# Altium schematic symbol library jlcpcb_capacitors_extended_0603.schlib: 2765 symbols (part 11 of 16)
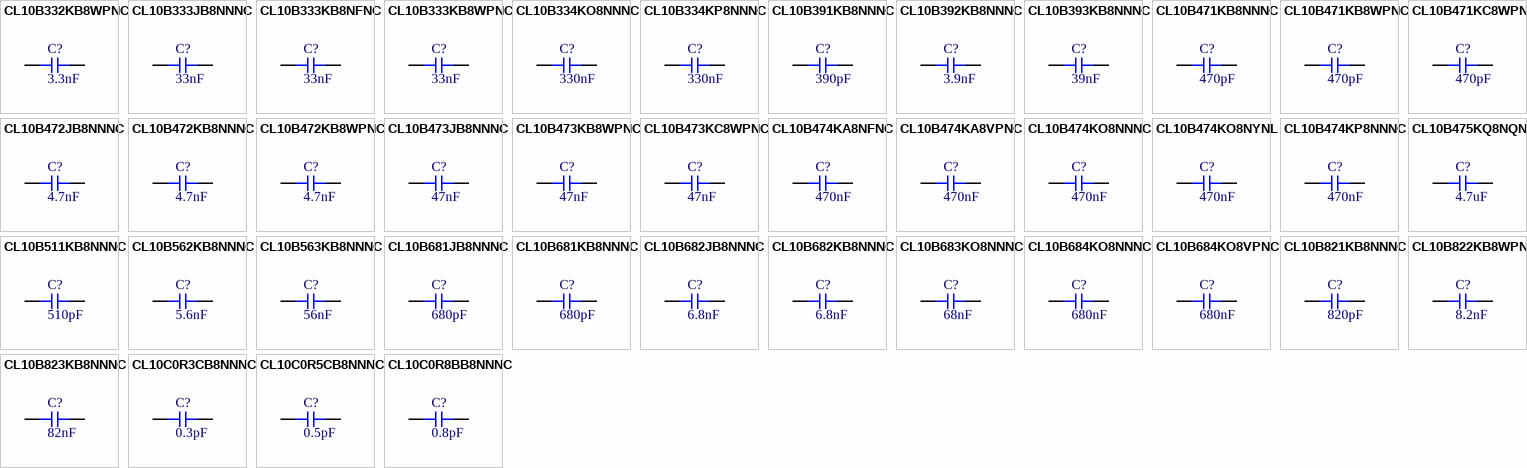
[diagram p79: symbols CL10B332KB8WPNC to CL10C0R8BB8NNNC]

## CL10B333KB8NFNC
designator C?  Capacitance: 33nF  (hidden comment: *)
Capacitor, Ceramic (MLCC), 33nF, ±10%, 50V, X7R, ±10%, SMD 0603; Manufacturer: Samsung Electro-Mechanics; Manufacturer Part Number: CL10B333KB8NFNC
footprint CAP-0603 (0603 (1608M) Capacitor)
pins: 1, 2

## CL10B333KB8WPNC
designator C?  Capacitance: 33nF  (hidden comment: *)
Capacitor, Ceramic (MLCC), 33nF, ±10%, 50V, X7R, ±10%, SMD 0603; Manufacturer: Samsung Electro-Mechanics; Manufacturer Part Number: CL10B333KB8WPNC
footprint CAP-0603 (0603 (1608M) Capacitor)
pins: 1, 2

## CL10B334KO8NNNC
designator C?  Capacitance: 330nF  (hidden comment: *)
Capacitor, Ceramic (MLCC), 330nF, ±10%, 16V, X7R, ±10%, SMD 0603; Manufacturer: Samsung Electro-Mechanics; Manufacturer Part Number: CL10B334KO8NNNC
footprint CAP-0603 (0603 (1608M) Capacitor)
pins: 1, 2

## CL10B334KP8NNNC
designator C?  Capacitance: 330nF  (hidden comment: *)
Capacitor, Ceramic (MLCC), 330nF, ±10%, 10V, X7R, ±10%, SMD 0603; Manufacturer: Samsung Electro-Mechanics; Manufacturer Part Number: CL10B334KP8NNNC
footprint CAP-0603 (0603 (1608M) Capacitor)
pins: 1, 2

## CL10B391KB8NNNC
designator C?  Capacitance: 390pF  (hidden comment: *)
Capacitor, Ceramic (MLCC), 390pF, ±10%, 50V, X7R, ±10%, SMD 0603; Manufacturer: Samsung Electro-Mechanics; Manufacturer Part Number: CL10B391KB8NNNC
footprint CAP-0603 (0603 (1608M) Capacitor)
pins: 1, 2

## CL10B392KB8NNNC
designator C?  Capacitance: 3.9nF  (hidden comment: *)
Capacitor, Ceramic (MLCC), 3.9nF, ±10%, 50V, X7R, ±10%, SMD 0603; Manufacturer: Samsung Electro-Mechanics; Manufacturer Part Number: CL10B392KB8NNNC
footprint CAP-0603 (0603 (1608M) Capacitor)
pins: 1, 2

## CL10B393KB8NNNC
designator C?  Capacitance: 39nF  (hidden comment: *)
Capacitor, Ceramic (MLCC), 39nF, ±10%, 50V, X7R, ±10%, SMD 0603; Manufacturer: Samsung Electro-Mechanics; Manufacturer Part Number: CL10B393KB8NNNC
footprint CAP-0603 (0603 (1608M) Capacitor)
pins: 1, 2

## CL10B471KB8NNNC
designator C?  Capacitance: 470pF  (hidden comment: *)
Capacitor, Ceramic (MLCC), 470pF, ±10%, 50V, X7R, ±10%, SMD 0603; Manufacturer: Samsung Electro-Mechanics; Manufacturer Part Number: CL10B471KB8NNNC
footprint CAP-0603 (0603 (1608M) Capacitor)
pins: 1, 2

## CL10B471KB8WPNC
designator C?  Capacitance: 470pF  (hidden comment: *)
Capacitor, Ceramic (MLCC), 470pF, ±10%, 50V, X7R, ±10%, SMD 0603; Manufacturer: Samsung Electro-Mechanics; Manufacturer Part Number: CL10B471KB8WPNC
footprint CAP-0603 (0603 (1608M) Capacitor)
pins: 1, 2

## CL10B471KC8WPNC
designator C?  Capacitance: 470pF  (hidden comment: *)
Capacitor, Ceramic (MLCC), 470pF, ±10%, 100V, X7R, ±10%, SMD 0603; Manufacturer: Samsung Electro-Mechanics; Manufacturer Part Number: CL10B471KC8WPNC
footprint CAP-0603 (0603 (1608M) Capacitor)
pins: 1, 2

## CL10B472JB8NNNC
designator C?  Capacitance: 4.7nF  (hidden comment: *)
Capacitor, Ceramic (MLCC), 4.7nF, ±5%, 50V, X7R, ±5%, SMD 0603; Manufacturer: Samsung Electro-Mechanics; Manufacturer Part Number: CL10B472JB8NNNC
footprint CAP-0603 (0603 (1608M) Capacitor)
pins: 1, 2

## CL10B472KB8NNNC
designator C?  Capacitance: 4.7nF  (hidden comment: *)
Capacitor, Ceramic (MLCC), 4.7nF, ±10%, 50V, X7R, ±10%, SMD 0603; Manufacturer: Samsung Electro-Mechanics; Manufacturer Part Number: CL10B472KB8NNNC
footprint CAP-0603 (0603 (1608M) Capacitor)
pins: 1, 2

## CL10B472KB8WPNC
designator C?  Capacitance: 4.7nF  (hidden comment: *)
Capacitor, Ceramic (MLCC), 4.7nF, ±10%, 50V, X7R, ±10%, SMD 0603; Manufacturer: Samsung Electro-Mechanics; Manufacturer Part Number: CL10B472KB8WPNC
footprint CAP-0603 (0603 (1608M) Capacitor)
pins: 1, 2

## CL10B473JB8NNNC
designator C?  Capacitance: 47nF  (hidden comment: *)
Capacitor, Ceramic (MLCC), 47nF, ±5%, 50V, X7R, ±5%, SMD 0603; Manufacturer: Samsung Electro-Mechanics; Manufacturer Part Number: CL10B473JB8NNNC
footprint CAP-0603 (0603 (1608M) Capacitor)
pins: 1, 2

## CL10B473KB8WPNC
designator C?  Capacitance: 47nF  (hidden comment: *)
Capacitor, Ceramic (MLCC), 47nF, ±10%, 50V, X7R, ±10%, SMD 0603; Manufacturer: Samsung Electro-Mechanics; Manufacturer Part Number: CL10B473KB8WPNC
footprint CAP-0603 (0603 (1608M) Capacitor)
pins: 1, 2

## CL10B473KC8WPNC
designator C?  Capacitance: 47nF  (hidden comment: *)
Capacitor, Ceramic (MLCC), 47nF, ±10%, 100V, X7R, ±10%, SMD 0603; Manufacturer: Samsung Electro-Mechanics; Manufacturer Part Number: CL10B473KC8WPNC
footprint CAP-0603 (0603 (1608M) Capacitor)
pins: 1, 2

## CL10B474KA8NFNC
designator C?  Capacitance: 470nF  (hidden comment: *)
Capacitor, Ceramic (MLCC), 470nF, ±10%, 25V, X7R, ±10%, SMD 0603; Manufacturer: Samsung Electro-Mechanics; Manufacturer Part Number: CL10B474KA8NFNC
footprint CAP-0603 (0603 (1608M) Capacitor)
pins: 1, 2

## CL10B474KA8VPNC
designator C?  Capacitance: 470nF  (hidden comment: *)
Capacitor, Ceramic (MLCC), 470nF, ±10%, 25V, X7R, ±10%, SMD 0603; Manufacturer: Samsung Electro-Mechanics; Manufacturer Part Number: CL10B474KA8VPNC
footprint CAP-0603 (0603 (1608M) Capacitor)
pins: 1, 2

## CL10B474KO8NNNC
designator C?  Capacitance: 470nF  (hidden comment: *)
Capacitor, Ceramic (MLCC), 470nF, ±10%, 16V, X7R, ±10%, SMD 0603; Manufacturer: Samsung Electro-Mechanics; Manufacturer Part Number: CL10B474KO8NNNC
footprint CAP-0603 (0603 (1608M) Capacitor)
pins: 1, 2

## CL10B474KO8NYNL
designator C?  Capacitance: 470nF  (hidden comment: *)
Capacitor, Ceramic (MLCC), 470nF, ±10%, 16V, X7R, ±10%, SMD 0603; Manufacturer: Samsung Electro-Mechanics; Manufacturer Part Number: CL10B474KO8NYNL
footprint CAP-0603 (0603 (1608M) Capacitor)
pins: 1, 2

## CL10B474KP8NNNC
designator C?  Capacitance: 470nF  (hidden comment: *)
Capacitor, Ceramic (MLCC), 470nF, ±10%, 10V, X7R, ±10%, SMD 0603; Manufacturer: Samsung Electro-Mechanics; Manufacturer Part Number: CL10B474KP8NNNC
footprint CAP-0603 (0603 (1608M) Capacitor)
pins: 1, 2

## CL10B475KQ8NQNC
designator C?  Capacitance: 4.7uF  (hidden comment: *)
Capacitor, Ceramic (MLCC), 4.7uF, ±10%, 6.3V, X7R, ±10%, SMD 0603; Manufacturer: Samsung Electro-Mechanics; Manufacturer Part Number: CL10B475KQ8NQNC
footprint CAP-0603 (0603 (1608M) Capacitor)
pins: 1, 2

## CL10B511KB8NNNC
designator C?  Capacitance: 510pF  (hidden comment: *)
Capacitor, Ceramic (MLCC), 510pF, ±10%, 50V, X7R, ±10%, SMD 0603; Manufacturer: Samsung Electro-Mechanics; Manufacturer Part Number: CL10B511KB8NNNC
footprint CAP-0603 (0603 (1608M) Capacitor)
pins: 1, 2

## CL10B562KB8NNNC
designator C?  Capacitance: 5.6nF  (hidden comment: *)
Capacitor, Ceramic (MLCC), 5.6nF, ±10%, 50V, X7R, ±10%, SMD 0603; Manufacturer: Samsung Electro-Mechanics; Manufacturer Part Number: CL10B562KB8NNNC
footprint CAP-0603 (0603 (1608M) Capacitor)
pins: 1, 2

## CL10B563KB8NNNC
designator C?  Capacitance: 56nF  (hidden comment: *)
Capacitor, Ceramic (MLCC), 56nF, ±10%, 50V, X7R, ±10%, SMD 0603; Manufacturer: Samsung Electro-Mechanics; Manufacturer Part Number: CL10B563KB8NNNC
footprint CAP-0603 (0603 (1608M) Capacitor)
pins: 1, 2

## CL10B681JB8NNNC
designator C?  Capacitance: 680pF  (hidden comment: *)
Capacitor, Ceramic (MLCC), 680pF, ±5%, 50V, X7R, ±5%, SMD 0603; Manufacturer: Samsung Electro-Mechanics; Manufacturer Part Number: CL10B681JB8NNNC
footprint CAP-0603 (0603 (1608M) Capacitor)
pins: 1, 2

## CL10B681KB8NNNC
designator C?  Capacitance: 680pF  (hidden comment: *)
Capacitor, Ceramic (MLCC), 680pF, ±10%, 50V, X7R, ±10%, SMD 0603; Manufacturer: Samsung Electro-Mechanics; Manufacturer Part Number: CL10B681KB8NNNC
footprint CAP-0603 (0603 (1608M) Capacitor)
pins: 1, 2

## CL10B682JB8NNNC
designator C?  Capacitance: 6.8nF  (hidden comment: *)
Capacitor, Ceramic (MLCC), 6.8nF, ±5%, 50V, X7R, ±5%, SMD 0603; Manufacturer: Samsung Electro-Mechanics; Manufacturer Part Number: CL10B682JB8NNNC
footprint CAP-0603 (0603 (1608M) Capacitor)
pins: 1, 2

## CL10B682KB8NNNC
designator C?  Capacitance: 6.8nF  (hidden comment: *)
Capacitor, Ceramic (MLCC), 6.8nF, ±10%, 50V, X7R, ±10%, SMD 0603; Manufacturer: Samsung Electro-Mechanics; Manufacturer Part Number: CL10B682KB8NNNC
footprint CAP-0603 (0603 (1608M) Capacitor)
pins: 1, 2

## CL10B683KO8NNNC
designator C?  Capacitance: 68nF  (hidden comment: *)
Capacitor, Ceramic (MLCC), 68nF, ±10%, 16V, X7R, ±10%, SMD 0603; Manufacturer: Samsung Electro-Mechanics; Manufacturer Part Number: CL10B683KO8NNNC
footprint CAP-0603 (0603 (1608M) Capacitor)
pins: 1, 2

## CL10B684KO8NNNC
designator C?  Capacitance: 680nF  (hidden comment: *)
Capacitor, Ceramic (MLCC), 680nF, ±10%, 16V, X7R, ±10%, SMD 0603; Manufacturer: Samsung Electro-Mechanics; Manufacturer Part Number: CL10B684KO8NNNC
footprint CAP-0603 (0603 (1608M) Capacitor)
pins: 1, 2

## CL10B684KO8VPNC
designator C?  Capacitance: 680nF  (hidden comment: *)
Capacitor, Ceramic (MLCC), 680nF, ±10%, 16V, X7R, ±10%, SMD 0603; Manufacturer: Samsung Electro-Mechanics; Manufacturer Part Number: CL10B684KO8VPNC
footprint CAP-0603 (0603 (1608M) Capacitor)
pins: 1, 2

## CL10B821KB8NNNC
designator C?  Capacitance: 820pF  (hidden comment: *)
Capacitor, Ceramic (MLCC), 820pF, ±10%, 50V, X7R, ±10%, SMD 0603; Manufacturer: Samsung Electro-Mechanics; Manufacturer Part Number: CL10B821KB8NNNC
footprint CAP-0603 (0603 (1608M) Capacitor)
pins: 1, 2

## CL10B822KB8WPNC
designator C?  Capacitance: 8.2nF  (hidden comment: *)
Capacitor, Ceramic (MLCC), 8.2nF, ±10%, 50V, X7R, ±10%, SMD 0603; Manufacturer: Samsung Electro-Mechanics; Manufacturer Part Number: CL10B822KB8WPNC
footprint CAP-0603 (0603 (1608M) Capacitor)
pins: 1, 2

## CL10B823KB8NNNC
designator C?  Capacitance: 82nF  (hidden comment: *)
Capacitor, Ceramic (MLCC), 82nF, ±10%, 50V, X7R, ±10%, SMD 0603; Manufacturer: Samsung Electro-Mechanics; Manufacturer Part Number: CL10B823KB8NNNC
footprint CAP-0603 (0603 (1608M) Capacitor)
pins: 1, 2

## CL10C0R3CB8NNNC
designator C?  Capacitance: 0.3pF  (hidden comment: *)
Capacitor, Ceramic (MLCC), 0.3pF, ±0.25pF, 50V, C0G, ±0.25pF, SMD 0603; Manufacturer: Samsung Electro-Mechanics; Manufacturer Part Number: CL10C0R3CB8NNNC
footprint CAP-0603 (0603 (1608M) Capacitor)
pins: 1, 2

## CL10C0R5CB8NNNC
designator C?  Capacitance: 0.5pF  (hidden comment: *)
Capacitor, Ceramic (MLCC), 0.5pF, ±0.25pF, 50V, C0G, ±0.25pF, SMD 0603; Manufacturer: Samsung Electro-Mechanics; Manufacturer Part Number: CL10C0R5CB8NNNC
footprint CAP-0603 (0603 (1608M) Capacitor)
pins: 1, 2

## CL10C0R8BB8NNNC
designator C?  Capacitance: 0.8pF  (hidden comment: *)
Capacitor, Ceramic (MLCC), 0.8pF, ±0.1pF, 50V, C0G, ±0.1pF, SMD 0603; Manufacturer: Samsung Electro-Mechanics; Manufacturer Part Number: CL10C0R8BB8NNNC
footprint CAP-0603 (0603 (1608M) Capacitor)
pins: 1, 2

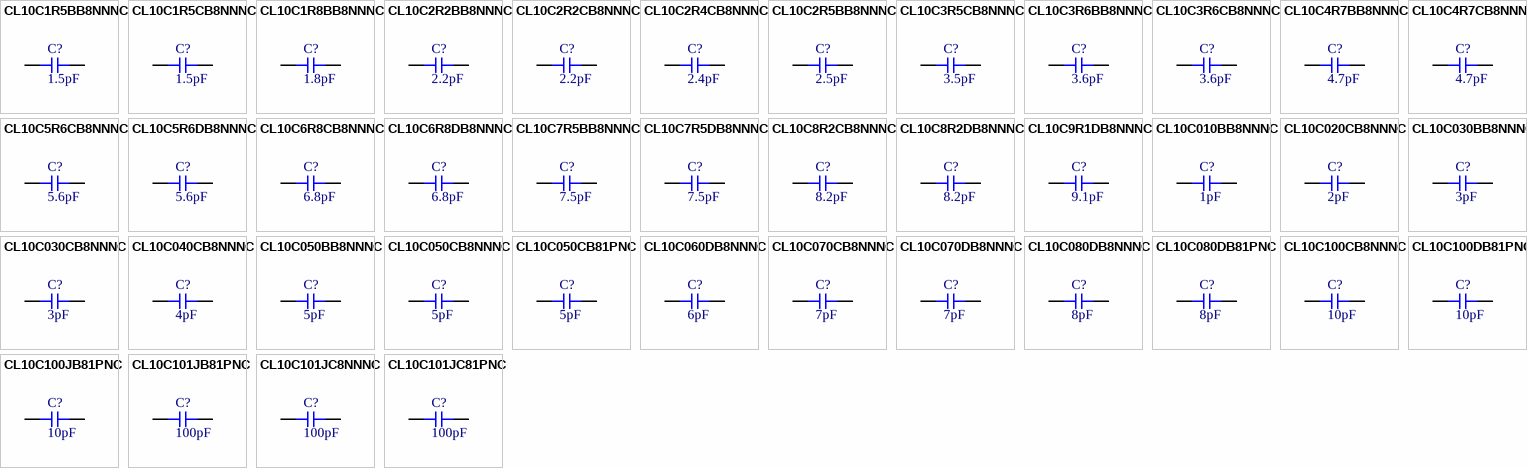
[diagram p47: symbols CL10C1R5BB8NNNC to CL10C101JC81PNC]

## CL10C1R5BB8NNNC
designator C?  Capacitance: 1.5pF  (hidden comment: *)
Capacitor, Ceramic (MLCC), 1.5pF, ±0.1pF, 50V, C0G, ±0.1pF, SMD 0603; Manufacturer: Samsung Electro-Mechanics; Manufacturer Part Number: CL10C1R5BB8NNNC
footprint CAP-0603 (0603 (1608M) Capacitor)
pins: 1, 2

## CL10C1R5CB8NNNC
designator C?  Capacitance: 1.5pF  (hidden comment: *)
Capacitor, Ceramic (MLCC), 1.5pF, ±0.25pF, 50V, C0G, ±0.25pF, SMD 0603; Manufacturer: Samsung Electro-Mechanics; Manufacturer Part Number: CL10C1R5CB8NNNC
footprint CAP-0603 (0603 (1608M) Capacitor)
pins: 1, 2

## CL10C1R8BB8NNNC
designator C?  Capacitance: 1.8pF  (hidden comment: *)
Capacitor, Ceramic (MLCC), 1.8pF, ±0.1pF, 50V, C0G, ±0.1pF, SMD 0603; Manufacturer: Samsung Electro-Mechanics; Manufacturer Part Number: CL10C1R8BB8NNNC
footprint CAP-0603 (0603 (1608M) Capacitor)
pins: 1, 2

## CL10C2R2BB8NNNC
designator C?  Capacitance: 2.2pF  (hidden comment: *)
Capacitor, Ceramic (MLCC), 2.2pF, ±0.1pF, 50V, C0G, ±0.1pF, SMD 0603; Manufacturer: Samsung Electro-Mechanics; Manufacturer Part Number: CL10C2R2BB8NNNC
footprint CAP-0603 (0603 (1608M) Capacitor)
pins: 1, 2

## CL10C2R2CB8NNNC
designator C?  Capacitance: 2.2pF  (hidden comment: *)
Capacitor, Ceramic (MLCC), 2.2pF, ±0.25pF, 50V, C0G, ±0.25pF, SMD 0603; Manufacturer: Samsung Electro-Mechanics; Manufacturer Part Number: CL10C2R2CB8NNNC
footprint CAP-0603 (0603 (1608M) Capacitor)
pins: 1, 2

## CL10C2R4CB8NNNC
designator C?  Capacitance: 2.4pF  (hidden comment: *)
Capacitor, Ceramic (MLCC), 2.4pF, ±0.25pF, 50V, C0G, ±0.25pF, SMD 0603; Manufacturer: Samsung Electro-Mechanics; Manufacturer Part Number: CL10C2R4CB8NNNC
footprint CAP-0603 (0603 (1608M) Capacitor)
pins: 1, 2

## CL10C2R5BB8NNNC
designator C?  Capacitance: 2.5pF  (hidden comment: *)
Capacitor, Ceramic (MLCC), 2.5pF, ±0.1pF, 50V, C0G, ±0.1pF, SMD 0603; Manufacturer: Samsung Electro-Mechanics; Manufacturer Part Number: CL10C2R5BB8NNNC
footprint CAP-0603 (0603 (1608M) Capacitor)
pins: 1, 2

## CL10C3R5CB8NNNC
designator C?  Capacitance: 3.5pF  (hidden comment: *)
Capacitor, Ceramic (MLCC), 3.5pF, ±0.25pF, 50V, C0G, ±0.25pF, SMD 0603; Manufacturer: Samsung Electro-Mechanics; Manufacturer Part Number: CL10C3R5CB8NNNC
footprint CAP-0603 (0603 (1608M) Capacitor)
pins: 1, 2

## CL10C3R6BB8NNNC
designator C?  Capacitance: 3.6pF  (hidden comment: *)
Capacitor, Ceramic (MLCC), 3.6pF, ±0.1pF, 50V, C0G, ±0.1pF, SMD 0603; Manufacturer: Samsung Electro-Mechanics; Manufacturer Part Number: CL10C3R6BB8NNNC
footprint CAP-0603 (0603 (1608M) Capacitor)
pins: 1, 2

## CL10C3R6CB8NNNC
designator C?  Capacitance: 3.6pF  (hidden comment: *)
Capacitor, Ceramic (MLCC), 3.6pF, ±0.25pF, 50V, C0G, ±0.25pF, SMD 0603; Manufacturer: Samsung Electro-Mechanics; Manufacturer Part Number: CL10C3R6CB8NNNC
footprint CAP-0603 (0603 (1608M) Capacitor)
pins: 1, 2

## CL10C4R7BB8NNNC
designator C?  Capacitance: 4.7pF  (hidden comment: *)
Capacitor, Ceramic (MLCC), 4.7pF, ±0.1pF, 50V, C0G, ±0.1pF, SMD 0603; Manufacturer: Samsung Electro-Mechanics; Manufacturer Part Number: CL10C4R7BB8NNNC
footprint CAP-0603 (0603 (1608M) Capacitor)
pins: 1, 2

## CL10C4R7CB8NNNC
designator C?  Capacitance: 4.7pF  (hidden comment: *)
Capacitor, Ceramic (MLCC), 4.7pF, ±0.25pF, 50V, C0G, ±0.25pF, SMD 0603; Manufacturer: Samsung Electro-Mechanics; Manufacturer Part Number: CL10C4R7CB8NNNC
footprint CAP-0603 (0603 (1608M) Capacitor)
pins: 1, 2

## CL10C5R6CB8NNNC
designator C?  Capacitance: 5.6pF  (hidden comment: *)
Capacitor, Ceramic (MLCC), 5.6pF, ±0.25pF, 50V, C0G, ±0.25pF, SMD 0603; Manufacturer: Samsung Electro-Mechanics; Manufacturer Part Number: CL10C5R6CB8NNNC
footprint CAP-0603 (0603 (1608M) Capacitor)
pins: 1, 2

## CL10C5R6DB8NNNC
designator C?  Capacitance: 5.6pF  (hidden comment: *)
Capacitor, Ceramic (MLCC), 5.6pF, ±0.5pF, 50V, C0G, ±0.5pF, SMD 0603; Manufacturer: Samsung Electro-Mechanics; Manufacturer Part Number: CL10C5R6DB8NNNC
footprint CAP-0603 (0603 (1608M) Capacitor)
pins: 1, 2

## CL10C6R8CB8NNNC
designator C?  Capacitance: 6.8pF  (hidden comment: *)
Capacitor, Ceramic (MLCC), 6.8pF, ±0.25pF, 50V, C0G, ±0.25pF, SMD 0603; Manufacturer: Samsung Electro-Mechanics; Manufacturer Part Number: CL10C6R8CB8NNNC
footprint CAP-0603 (0603 (1608M) Capacitor)
pins: 1, 2

## CL10C6R8DB8NNNC
designator C?  Capacitance: 6.8pF  (hidden comment: *)
Capacitor, Ceramic (MLCC), 6.8pF, ±0.5pF, 50V, C0G, ±0.5pF, SMD 0603; Manufacturer: Samsung Electro-Mechanics; Manufacturer Part Number: CL10C6R8DB8NNNC
footprint CAP-0603 (0603 (1608M) Capacitor)
pins: 1, 2

## CL10C7R5BB8NNNC
designator C?  Capacitance: 7.5pF  (hidden comment: *)
Capacitor, Ceramic (MLCC), 7.5pF, ±0.1pF, 50V, C0G, ±0.1pF, SMD 0603; Manufacturer: Samsung Electro-Mechanics; Manufacturer Part Number: CL10C7R5BB8NNNC
footprint CAP-0603 (0603 (1608M) Capacitor)
pins: 1, 2

## CL10C7R5DB8NNNC
designator C?  Capacitance: 7.5pF  (hidden comment: *)
Capacitor, Ceramic (MLCC), 7.5pF, ±0.5pF, 50V, C0G, ±0.5pF, SMD 0603; Manufacturer: Samsung Electro-Mechanics; Manufacturer Part Number: CL10C7R5DB8NNNC
footprint CAP-0603 (0603 (1608M) Capacitor)
pins: 1, 2

## CL10C8R2CB8NNNC
designator C?  Capacitance: 8.2pF  (hidden comment: *)
Capacitor, Ceramic (MLCC), 8.2pF, ±0.25pF, 50V, C0G, ±0.25pF, SMD 0603; Manufacturer: Samsung Electro-Mechanics; Manufacturer Part Number: CL10C8R2CB8NNNC
footprint CAP-0603 (0603 (1608M) Capacitor)
pins: 1, 2

## CL10C8R2DB8NNNC
designator C?  Capacitance: 8.2pF  (hidden comment: *)
Capacitor, Ceramic (MLCC), 8.2pF, ±0.5pF, 50V, C0G, ±0.5pF, SMD 0603; Manufacturer: Samsung Electro-Mechanics; Manufacturer Part Number: CL10C8R2DB8NNNC
footprint CAP-0603 (0603 (1608M) Capacitor)
pins: 1, 2

## CL10C9R1DB8NNNC
designator C?  Capacitance: 9.1pF  (hidden comment: *)
Capacitor, Ceramic (MLCC), 9.1pF, ±0.5pF, 50V, C0G, ±0.5pF, SMD 0603; Manufacturer: Samsung Electro-Mechanics; Manufacturer Part Number: CL10C9R1DB8NNNC
footprint CAP-0603 (0603 (1608M) Capacitor)
pins: 1, 2

## CL10C010BB8NNNC
designator C?  Capacitance: 1pF  (hidden comment: *)
Capacitor, Ceramic (MLCC), 1pF, ±0.1pF, 50V, C0G, ±0.1pF, SMD 0603; Manufacturer: Samsung Electro-Mechanics; Manufacturer Part Number: CL10C010BB8NNNC
footprint CAP-0603 (0603 (1608M) Capacitor)
pins: 1, 2

## CL10C020CB8NNNC
designator C?  Capacitance: 2pF  (hidden comment: *)
Capacitor, Ceramic (MLCC), 2pF, ±0.25pF, 50V, C0G, ±0.25pF, SMD 0603; Manufacturer: Samsung Electro-Mechanics; Manufacturer Part Number: CL10C020CB8NNNC
footprint CAP-0603 (0603 (1608M) Capacitor)
pins: 1, 2

## CL10C030BB8NNNC
designator C?  Capacitance: 3pF  (hidden comment: *)
Capacitor, Ceramic (MLCC), 3pF, ±0.1pF, 50V, C0G, ±0.1pF, SMD 0603; Manufacturer: Samsung Electro-Mechanics; Manufacturer Part Number: CL10C030BB8NNNC
footprint CAP-0603 (0603 (1608M) Capacitor)
pins: 1, 2

## CL10C030CB8NNNC
designator C?  Capacitance: 3pF  (hidden comment: *)
Capacitor, Ceramic (MLCC), 3pF, ±0.25pF, 50V, C0G, ±0.25pF, SMD 0603; Manufacturer: Samsung Electro-Mechanics; Manufacturer Part Number: CL10C030CB8NNNC
footprint CAP-0603 (0603 (1608M) Capacitor)
pins: 1, 2

## CL10C040CB8NNNC
designator C?  Capacitance: 4pF  (hidden comment: *)
Capacitor, Ceramic (MLCC), 4pF, ±0.25pF, 50V, C0G, ±0.25pF, SMD 0603; Manufacturer: Samsung Electro-Mechanics; Manufacturer Part Number: CL10C040CB8NNNC
footprint CAP-0603 (0603 (1608M) Capacitor)
pins: 1, 2

## CL10C050BB8NNNC
designator C?  Capacitance: 5pF  (hidden comment: *)
Capacitor, Ceramic (MLCC), 5pF, ±0.1pF, 50V, C0G, ±0.1pF, SMD 0603; Manufacturer: Samsung Electro-Mechanics; Manufacturer Part Number: CL10C050BB8NNNC
footprint CAP-0603 (0603 (1608M) Capacitor)
pins: 1, 2

## CL10C050CB8NNNC
designator C?  Capacitance: 5pF  (hidden comment: *)
Capacitor, Ceramic (MLCC), 5pF, ±0.25pF, 50V, C0G, ±0.25pF, SMD 0603; Manufacturer: Samsung Electro-Mechanics; Manufacturer Part Number: CL10C050CB8NNNC
footprint CAP-0603 (0603 (1608M) Capacitor)
pins: 1, 2

## CL10C050CB81PNC
designator C?  Capacitance: 5pF  (hidden comment: *)
Capacitor, Ceramic (MLCC), 5pF, ±0.25pF, 50V, C0G, ±0.25pF, SMD 0603; Manufacturer: Samsung Electro-Mechanics; Manufacturer Part Number: CL10C050CB81PNC
footprint CAP-0603 (0603 (1608M) Capacitor)
pins: 1, 2

## CL10C060DB8NNNC
designator C?  Capacitance: 6pF  (hidden comment: *)
Capacitor, Ceramic (MLCC), 6pF, ±0.5pF, 50V, C0G, ±0.5pF, SMD 0603; Manufacturer: Samsung Electro-Mechanics; Manufacturer Part Number: CL10C060DB8NNNC
footprint CAP-0603 (0603 (1608M) Capacitor)
pins: 1, 2

## CL10C070CB8NNNC
designator C?  Capacitance: 7pF  (hidden comment: *)
Capacitor, Ceramic (MLCC), 7pF, ±0.25pF, 50V, C0G, ±0.25pF, SMD 0603; Manufacturer: Samsung Electro-Mechanics; Manufacturer Part Number: CL10C070CB8NNNC
footprint CAP-0603 (0603 (1608M) Capacitor)
pins: 1, 2

## CL10C070DB8NNNC
designator C?  Capacitance: 7pF  (hidden comment: *)
Capacitor, Ceramic (MLCC), 7pF, ±0.5pF, 50V, C0G, ±0.5pF, SMD 0603; Manufacturer: Samsung Electro-Mechanics; Manufacturer Part Number: CL10C070DB8NNNC
footprint CAP-0603 (0603 (1608M) Capacitor)
pins: 1, 2

## CL10C080DB8NNNC
designator C?  Capacitance: 8pF  (hidden comment: *)
Capacitor, Ceramic (MLCC), 8pF, ±0.5pF, 50V, C0G, ±0.5pF, SMD 0603; Manufacturer: Samsung Electro-Mechanics; Manufacturer Part Number: CL10C080DB8NNNC
footprint CAP-0603 (0603 (1608M) Capacitor)
pins: 1, 2

## CL10C080DB81PNC
designator C?  Capacitance: 8pF  (hidden comment: *)
Capacitor, Ceramic (MLCC), 8pF, ±0.5pF, 50V, C0G, ±0.5pF, SMD 0603; Manufacturer: Samsung Electro-Mechanics; Manufacturer Part Number: CL10C080DB81PNC
footprint CAP-0603 (0603 (1608M) Capacitor)
pins: 1, 2

## CL10C100CB8NNNC
designator C?  Capacitance: 10pF  (hidden comment: *)
Capacitor, Ceramic (MLCC), 10pF, ±0.25pF, 50V, C0G, ±0.25pF, SMD 0603; Manufacturer: Samsung Electro-Mechanics; Manufacturer Part Number: CL10C100CB8NNNC
footprint CAP-0603 (0603 (1608M) Capacitor)
pins: 1, 2

## CL10C100DB81PNC
designator C?  Capacitance: 10pF  (hidden comment: *)
Capacitor, Ceramic (MLCC), 10pF, ±0.5pF, 50V, C0G, ±0.5pF, SMD 0603; Manufacturer: Samsung Electro-Mechanics; Manufacturer Part Number: CL10C100DB81PNC
footprint CAP-0603 (0603 (1608M) Capacitor)
pins: 1, 2

## CL10C100JB81PNC
designator C?  Capacitance: 10pF  (hidden comment: *)
Capacitor, Ceramic (MLCC), 10pF, ±5%, 50V, C0G, ±5%, SMD 0603; Manufacturer: Samsung Electro-Mechanics; Manufacturer Part Number: CL10C100JB81PNC
footprint CAP-0603 (0603 (1608M) Capacitor)
pins: 1, 2

## CL10C101JB81PNC
designator C?  Capacitance: 100pF  (hidden comment: *)
Capacitor, Ceramic (MLCC), 100pF, ±5%, 50V, C0G, ±5%, SMD 0603; Manufacturer: Samsung Electro-Mechanics; Manufacturer Part Number: CL10C101JB81PNC
footprint CAP-0603 (0603 (1608M) Capacitor)
pins: 1, 2

## CL10C101JC8NNNC
designator C?  Capacitance: 100pF  (hidden comment: *)
Capacitor, Ceramic (MLCC), 100pF, ±5%, 100V, C0G, ±5%, SMD 0603; Manufacturer: Samsung Electro-Mechanics; Manufacturer Part Number: CL10C101JC8NNNC
footprint CAP-0603 (0603 (1608M) Capacitor)
pins: 1, 2

## CL10C101JC81PNC
designator C?  Capacitance: 100pF  (hidden comment: *)
Capacitor, Ceramic (MLCC), 100pF, ±5%, 100V, C0G, ±5%, SMD 0603; Manufacturer: Samsung Electro-Mechanics; Manufacturer Part Number: CL10C101JC81PNC
footprint CAP-0603 (0603 (1608M) Capacitor)
pins: 1, 2

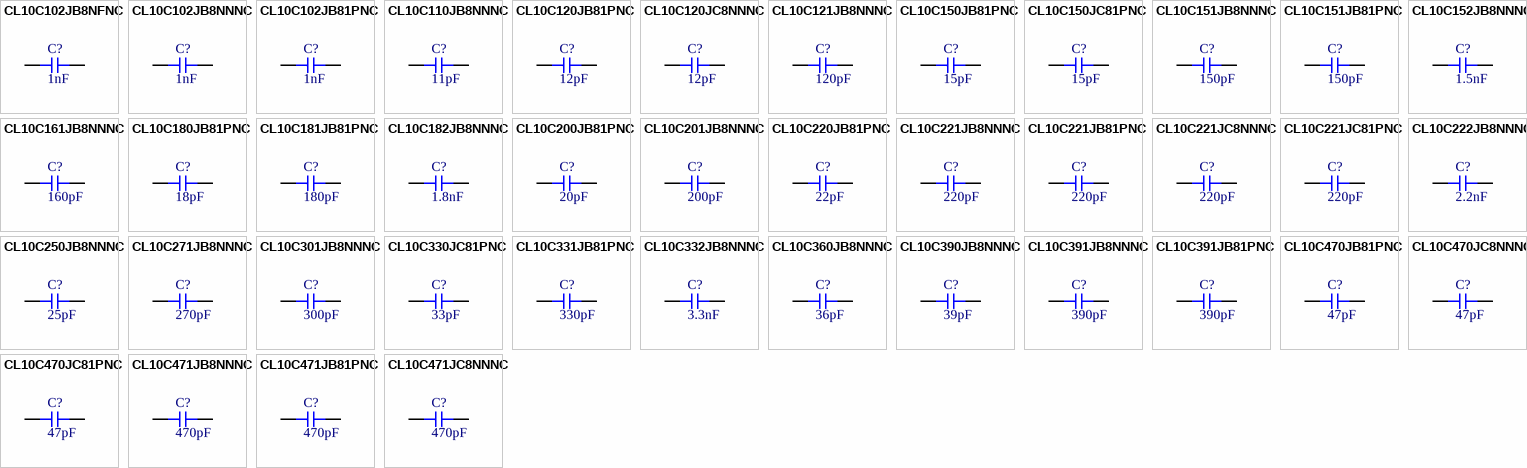
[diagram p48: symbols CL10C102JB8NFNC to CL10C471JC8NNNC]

## CL10C102JB8NFNC
designator C?  Capacitance: 1nF  (hidden comment: *)
Capacitor, Ceramic (MLCC), 1nF, ±5%, 50V, C0G, ±5%, SMD 0603; Manufacturer: Samsung Electro-Mechanics; Manufacturer Part Number: CL10C102JB8NFNC
footprint CAP-0603 (0603 (1608M) Capacitor)
pins: 1, 2

## CL10C102JB8NNNC
designator C?  Capacitance: 1nF  (hidden comment: *)
Capacitor, Ceramic (MLCC), 1nF, ±5%, 50V, C0G, ±5%, SMD 0603; Manufacturer: Samsung Electro-Mechanics; Manufacturer Part Number: CL10C102JB8NNNC
footprint CAP-0603 (0603 (1608M) Capacitor)
pins: 1, 2

## CL10C102JB81PNC
designator C?  Capacitance: 1nF  (hidden comment: *)
Capacitor, Ceramic (MLCC), 1nF, ±5%, 50V, C0G, ±5%, SMD 0603; Manufacturer: Samsung Electro-Mechanics; Manufacturer Part Number: CL10C102JB81PNC
footprint CAP-0603 (0603 (1608M) Capacitor)
pins: 1, 2

## CL10C110JB8NNNC
designator C?  Capacitance: 11pF  (hidden comment: *)
Capacitor, Ceramic (MLCC), 11pF, ±5%, 50V, C0G, ±5%, SMD 0603; Manufacturer: Samsung Electro-Mechanics; Manufacturer Part Number: CL10C110JB8NNNC
footprint CAP-0603 (0603 (1608M) Capacitor)
pins: 1, 2

## CL10C120JB81PNC
designator C?  Capacitance: 12pF  (hidden comment: *)
Capacitor, Ceramic (MLCC), 12pF, ±5%, 50V, C0G, ±5%, SMD 0603; Manufacturer: Samsung Electro-Mechanics; Manufacturer Part Number: CL10C120JB81PNC
footprint CAP-0603 (0603 (1608M) Capacitor)
pins: 1, 2

## CL10C120JC8NNNC
designator C?  Capacitance: 12pF  (hidden comment: *)
Capacitor, Ceramic (MLCC), 12pF, ±5%, 100V, C0G, ±5%, SMD 0603; Manufacturer: Samsung Electro-Mechanics; Manufacturer Part Number: CL10C120JC8NNNC
footprint CAP-0603 (0603 (1608M) Capacitor)
pins: 1, 2

## CL10C121JB8NNNC
designator C?  Capacitance: 120pF  (hidden comment: *)
Capacitor, Ceramic (MLCC), 120pF, ±5%, 50V, C0G, ±5%, SMD 0603; Manufacturer: Samsung Electro-Mechanics; Manufacturer Part Number: CL10C121JB8NNNC
footprint CAP-0603 (0603 (1608M) Capacitor)
pins: 1, 2

## CL10C150JB81PNC
designator C?  Capacitance: 15pF  (hidden comment: *)
Capacitor, Ceramic (MLCC), 15pF, ±5%, 50V, ±5%, SMD 0603; Manufacturer: Samsung Electro-Mechanics; Manufacturer Part Number: CL10C150JB81PNC
footprint CAP-0603 (0603 (1608M) Capacitor)
pins: 1, 2

## CL10C150JC81PNC
designator C?  Capacitance: 15pF  (hidden comment: *)
Capacitor, Ceramic (MLCC), 15pF, ±5%, 100V, C0G, ±5%, SMD 0603; Manufacturer: Samsung Electro-Mechanics; Manufacturer Part Number: CL10C150JC81PNC
footprint CAP-0603 (0603 (1608M) Capacitor)
pins: 1, 2

## CL10C151JB8NNNC
designator C?  Capacitance: 150pF  (hidden comment: *)
Capacitor, Ceramic (MLCC), 150pF, ±5%, 50V, C0G, ±5%, SMD 0603; Manufacturer: Samsung Electro-Mechanics; Manufacturer Part Number: CL10C151JB8NNNC
footprint CAP-0603 (0603 (1608M) Capacitor)
pins: 1, 2

## CL10C151JB81PNC
designator C?  Capacitance: 150pF  (hidden comment: *)
Capacitor, Ceramic (MLCC), 150pF, ±5%, 50V, C0G, ±5%, SMD 0603; Manufacturer: Samsung Electro-Mechanics; Manufacturer Part Number: CL10C151JB81PNC
footprint CAP-0603 (0603 (1608M) Capacitor)
pins: 1, 2

## CL10C152JB8NNNC
designator C?  Capacitance: 1.5nF  (hidden comment: *)
Capacitor, Ceramic (MLCC), 1.5nF, ±5%, 50V, C0G, ±5%, SMD 0603; Manufacturer: Samsung Electro-Mechanics; Manufacturer Part Number: CL10C152JB8NNNC
footprint CAP-0603 (0603 (1608M) Capacitor)
pins: 1, 2

## CL10C161JB8NNNC
designator C?  Capacitance: 160pF  (hidden comment: *)
Capacitor, Ceramic (MLCC), 160pF, ±5%, 50V, C0G, ±5%, SMD 0603; Manufacturer: Samsung Electro-Mechanics; Manufacturer Part Number: CL10C161JB8NNNC
footprint CAP-0603 (0603 (1608M) Capacitor)
pins: 1, 2

## CL10C180JB81PNC
designator C?  Capacitance: 18pF  (hidden comment: *)
Capacitor, Ceramic (MLCC), 18pF, ±5%, 50V, C0G, ±5%, SMD 0603; Manufacturer: Samsung Electro-Mechanics; Manufacturer Part Number: CL10C180JB81PNC
footprint CAP-0603 (0603 (1608M) Capacitor)
pins: 1, 2

## CL10C181JB81PNC
designator C?  Capacitance: 180pF  (hidden comment: *)
Capacitor, Ceramic (MLCC), 180pF, ±5%, 50V, C0G, ±5%, SMD 0603; Manufacturer: Samsung Electro-Mechanics; Manufacturer Part Number: CL10C181JB81PNC
footprint CAP-0603 (0603 (1608M) Capacitor)
pins: 1, 2

## CL10C182JB8NNNC
designator C?  Capacitance: 1.8nF  (hidden comment: *)
Capacitor, Ceramic (MLCC), 1.8nF, ±5%, 50V, C0G, ±5%, SMD 0603; Manufacturer: Samsung Electro-Mechanics; Manufacturer Part Number: CL10C182JB8NNNC
footprint CAP-0603 (0603 (1608M) Capacitor)
pins: 1, 2

## CL10C200JB81PNC
designator C?  Capacitance: 20pF  (hidden comment: *)
Capacitor, Ceramic (MLCC), 20pF, ±5%, 50V, C0G, ±5%, SMD 0603; Manufacturer: Samsung Electro-Mechanics; Manufacturer Part Number: CL10C200JB81PNC
footprint CAP-0603 (0603 (1608M) Capacitor)
pins: 1, 2

## CL10C201JB8NNNC
designator C?  Capacitance: 200pF  (hidden comment: *)
Capacitor, Ceramic (MLCC), 200pF, ±5%, 50V, C0G, ±5%, SMD 0603; Manufacturer: Samsung Electro-Mechanics; Manufacturer Part Number: CL10C201JB8NNNC
footprint CAP-0603 (0603 (1608M) Capacitor)
pins: 1, 2

## CL10C220JB81PNC
designator C?  Capacitance: 22pF  (hidden comment: *)
Capacitor, Ceramic (MLCC), 22pF, ±5%, 50V, C0G, ±5%, SMD 0603; Manufacturer: Samsung Electro-Mechanics; Manufacturer Part Number: CL10C220JB81PNC
footprint CAP-0603 (0603 (1608M) Capacitor)
pins: 1, 2

## CL10C221JB8NNNC
designator C?  Capacitance: 220pF  (hidden comment: *)
Capacitor, Ceramic (MLCC), 220pF, ±5%, 50V, C0G, ±5%, SMD 0603; Manufacturer: Samsung Electro-Mechanics; Manufacturer Part Number: CL10C221JB8NNNC
footprint CAP-0603 (0603 (1608M) Capacitor)
pins: 1, 2

## CL10C221JB81PNC
designator C?  Capacitance: 220pF  (hidden comment: *)
Capacitor, Ceramic (MLCC), 220pF, ±5%, 50V, C0G, ±5%, SMD 0603; Manufacturer: Samsung Electro-Mechanics; Manufacturer Part Number: CL10C221JB81PNC
footprint CAP-0603 (0603 (1608M) Capacitor)
pins: 1, 2

## CL10C221JC8NNNC
designator C?  Capacitance: 220pF  (hidden comment: *)
Capacitor, Ceramic (MLCC), 220pF, ±5%, 100V, C0G, ±5%, SMD 0603; Manufacturer: Samsung Electro-Mechanics; Manufacturer Part Number: CL10C221JC8NNNC
footprint CAP-0603 (0603 (1608M) Capacitor)
pins: 1, 2

## CL10C221JC81PNC
designator C?  Capacitance: 220pF  (hidden comment: *)
Capacitor, Ceramic (MLCC), 220pF, ±5%, 100V, C0G, ±5%, SMD 0603; Manufacturer: Samsung Electro-Mechanics; Manufacturer Part Number: CL10C221JC81PNC
footprint CAP-0603 (0603 (1608M) Capacitor)
pins: 1, 2

## CL10C222JB8NNNC
designator C?  Capacitance: 2.2nF  (hidden comment: *)
Capacitor, Ceramic (MLCC), 2.2nF, ±5%, 50V, C0G, ±5%, SMD 0603; Manufacturer: Samsung Electro-Mechanics; Manufacturer Part Number: CL10C222JB8NNNC
footprint CAP-0603 (0603 (1608M) Capacitor)
pins: 1, 2

## CL10C250JB8NNNC
designator C?  Capacitance: 25pF  (hidden comment: *)
Capacitor, Ceramic (MLCC), 25pF, ±5%, 50V, C0G, ±5%, SMD 0603; Manufacturer: Samsung Electro-Mechanics; Manufacturer Part Number: CL10C250JB8NNNC
footprint CAP-0603 (0603 (1608M) Capacitor)
pins: 1, 2

## CL10C271JB8NNNC
designator C?  Capacitance: 270pF  (hidden comment: *)
Capacitor, Ceramic (MLCC), 270pF, ±5%, 50V, C0G, ±5%, SMD 0603; Manufacturer: Samsung Electro-Mechanics; Manufacturer Part Number: CL10C271JB8NNNC
footprint CAP-0603 (0603 (1608M) Capacitor)
pins: 1, 2

## CL10C301JB8NNNC
designator C?  Capacitance: 300pF  (hidden comment: *)
Capacitor, Ceramic (MLCC), 300pF, ±5%, 50V, C0G, ±5%, SMD 0603; Manufacturer: Samsung Electro-Mechanics; Manufacturer Part Number: CL10C301JB8NNNC
footprint CAP-0603 (0603 (1608M) Capacitor)
pins: 1, 2

## CL10C330JC81PNC
designator C?  Capacitance: 33pF  (hidden comment: *)
Capacitor, Ceramic (MLCC), 33pF, ±5%, 100V, C0G, ±5%, SMD 0603; Manufacturer: Samsung Electro-Mechanics; Manufacturer Part Number: CL10C330JC81PNC
footprint CAP-0603 (0603 (1608M) Capacitor)
pins: 1, 2

## CL10C331JB81PNC
designator C?  Capacitance: 330pF  (hidden comment: *)
Capacitor, Ceramic (MLCC), 330pF, ±5%, 50V, C0G, ±5%, SMD 0603; Manufacturer: Samsung Electro-Mechanics; Manufacturer Part Number: CL10C331JB81PNC
footprint CAP-0603 (0603 (1608M) Capacitor)
pins: 1, 2

## CL10C332JB8NNNC
designator C?  Capacitance: 3.3nF  (hidden comment: *)
Capacitor, Ceramic (MLCC), 3.3nF, ±5%, 50V, C0G, ±5%, SMD 0603; Manufacturer: Samsung Electro-Mechanics; Manufacturer Part Number: CL10C332JB8NNNC
footprint CAP-0603 (0603 (1608M) Capacitor)
pins: 1, 2

## CL10C360JB8NNNC
designator C?  Capacitance: 36pF  (hidden comment: *)
Capacitor, Ceramic (MLCC), 36pF, ±5%, 50V, C0G, ±5%, SMD 0603; Manufacturer: Samsung Electro-Mechanics; Manufacturer Part Number: CL10C360JB8NNNC
footprint CAP-0603 (0603 (1608M) Capacitor)
pins: 1, 2

## CL10C390JB8NNNC
designator C?  Capacitance: 39pF  (hidden comment: *)
Capacitor, Ceramic (MLCC), 39pF, ±5%, 50V, C0G, ±5%, SMD 0603; Manufacturer: Samsung Electro-Mechanics; Manufacturer Part Number: CL10C390JB8NNNC
footprint CAP-0603 (0603 (1608M) Capacitor)
pins: 1, 2

## CL10C391JB8NNNC
designator C?  Capacitance: 390pF  (hidden comment: *)
Capacitor, Ceramic (MLCC), 390pF, ±5%, 50V, C0G, ±5%, SMD 0603; Manufacturer: Samsung Electro-Mechanics; Manufacturer Part Number: CL10C391JB8NNNC
footprint CAP-0603 (0603 (1608M) Capacitor)
pins: 1, 2

## CL10C391JB81PNC
designator C?  Capacitance: 390pF  (hidden comment: *)
Capacitor, Ceramic (MLCC), 390pF, ±5%, 50V, C0G, ±5%, SMD 0603; Manufacturer: Samsung Electro-Mechanics; Manufacturer Part Number: CL10C391JB81PNC
footprint CAP-0603 (0603 (1608M) Capacitor)
pins: 1, 2

## CL10C470JB81PNC
designator C?  Capacitance: 47pF  (hidden comment: *)
Capacitor, Ceramic (MLCC), 47pF, ±5%, 50V, C0G, ±5%, SMD 0603; Manufacturer: Samsung Electro-Mechanics; Manufacturer Part Number: CL10C470JB81PNC
footprint CAP-0603 (0603 (1608M) Capacitor)
pins: 1, 2

## CL10C470JC8NNNC
designator C?  Capacitance: 47pF  (hidden comment: *)
Capacitor, Ceramic (MLCC), 47pF, ±5%, 100V, C0G, ±5%, SMD 0603; Manufacturer: Samsung Electro-Mechanics; Manufacturer Part Number: CL10C470JC8NNNC
footprint CAP-0603 (0603 (1608M) Capacitor)
pins: 1, 2

## CL10C470JC81PNC
designator C?  Capacitance: 47pF  (hidden comment: *)
Capacitor, Ceramic (MLCC), 47pF, ±5%, 100V, C0G, ±5%, SMD 0603; Manufacturer: Samsung Electro-Mechanics; Manufacturer Part Number: CL10C470JC81PNC
footprint CAP-0603 (0603 (1608M) Capacitor)
pins: 1, 2

## CL10C471JB8NNNC
designator C?  Capacitance: 470pF  (hidden comment: *)
Capacitor, Ceramic (MLCC), 470pF, ±5%, 50V, C0G, ±5%, SMD 0603; Manufacturer: Samsung Electro-Mechanics; Manufacturer Part Number: CL10C471JB8NNNC
footprint CAP-0603 (0603 (1608M) Capacitor)
pins: 1, 2

## CL10C471JB81PNC
designator C?  Capacitance: 470pF  (hidden comment: *)
Capacitor, Ceramic (MLCC), 470pF, ±5%, 50V, C0G, ±5%, SMD 0603; Manufacturer: Samsung Electro-Mechanics; Manufacturer Part Number: CL10C471JB81PNC
footprint CAP-0603 (0603 (1608M) Capacitor)
pins: 1, 2

## CL10C471JC8NNNC
designator C?  Capacitance: 470pF  (hidden comment: *)
Capacitor, Ceramic (MLCC), 470pF, ±5%, 100V, C0G, ±5%, SMD 0603; Manufacturer: Samsung Electro-Mechanics; Manufacturer Part Number: CL10C471JC8NNNC
footprint CAP-0603 (0603 (1608M) Capacitor)
pins: 1, 2

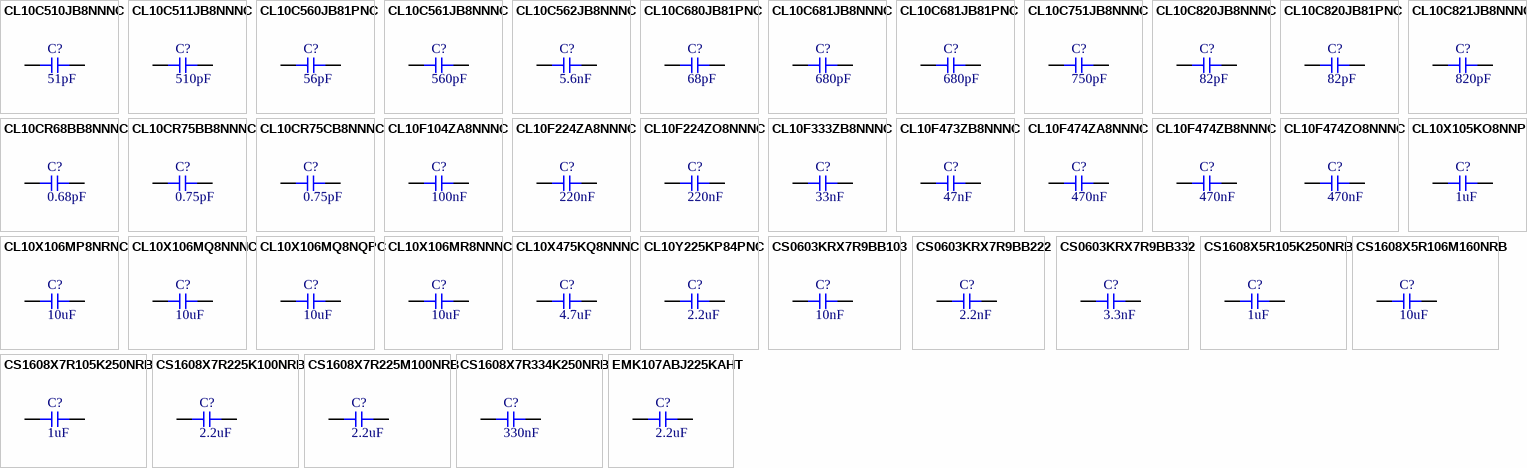
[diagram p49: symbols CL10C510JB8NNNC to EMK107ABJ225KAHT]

## CL10C510JB8NNNC
designator C?  Capacitance: 51pF  (hidden comment: *)
Capacitor, Ceramic (MLCC), 51pF, ±5%, 50V, C0G, ±5%, SMD 0603; Manufacturer: Samsung Electro-Mechanics; Manufacturer Part Number: CL10C510JB8NNNC
footprint CAP-0603 (0603 (1608M) Capacitor)
pins: 1, 2

## CL10C511JB8NNNC
designator C?  Capacitance: 510pF  (hidden comment: *)
Capacitor, Ceramic (MLCC), 510pF, ±5%, 50V, C0G, ±5%, SMD 0603; Manufacturer: Samsung Electro-Mechanics; Manufacturer Part Number: CL10C511JB8NNNC
footprint CAP-0603 (0603 (1608M) Capacitor)
pins: 1, 2

## CL10C560JB81PNC
designator C?  Capacitance: 56pF  (hidden comment: *)
Capacitor, Ceramic (MLCC), 56pF, ±5%, 50V, C0G, ±5%, SMD 0603; Manufacturer: Samsung Electro-Mechanics; Manufacturer Part Number: CL10C560JB81PNC
footprint CAP-0603 (0603 (1608M) Capacitor)
pins: 1, 2

## CL10C561JB8NNNC
designator C?  Capacitance: 560pF  (hidden comment: *)
Capacitor, Ceramic (MLCC), 560pF, ±5%, 50V, C0G, ±5%, SMD 0603; Manufacturer: Samsung Electro-Mechanics; Manufacturer Part Number: CL10C561JB8NNNC
footprint CAP-0603 (0603 (1608M) Capacitor)
pins: 1, 2

## CL10C562JB8NNNC
designator C?  Capacitance: 5.6nF  (hidden comment: *)
Capacitor, Ceramic (MLCC), 5.6nF, ±5%, 50V, C0G, ±5%, SMD 0603; Manufacturer: Samsung Electro-Mechanics; Manufacturer Part Number: CL10C562JB8NNNC
footprint CAP-0603 (0603 (1608M) Capacitor)
pins: 1, 2

## CL10C680JB81PNC
designator C?  Capacitance: 68pF  (hidden comment: *)
Capacitor, Ceramic (MLCC), 68pF, ±5%, 50V, C0G, ±5%, SMD 0603; Manufacturer: Samsung Electro-Mechanics; Manufacturer Part Number: CL10C680JB81PNC
footprint CAP-0603 (0603 (1608M) Capacitor)
pins: 1, 2

## CL10C681JB8NNNC
designator C?  Capacitance: 680pF  (hidden comment: *)
Capacitor, Ceramic (MLCC), 680pF, ±5%, 50V, C0G, ±5%, SMD 0603; Manufacturer: Samsung Electro-Mechanics; Manufacturer Part Number: CL10C681JB8NNNC
footprint CAP-0603 (0603 (1608M) Capacitor)
pins: 1, 2

## CL10C681JB81PNC
designator C?  Capacitance: 680pF  (hidden comment: *)
Capacitor, Ceramic (MLCC), 680pF, ±5%, 50V, C0G, ±5%, SMD 0603; Manufacturer: Samsung Electro-Mechanics; Manufacturer Part Number: CL10C681JB81PNC
footprint CAP-0603 (0603 (1608M) Capacitor)
pins: 1, 2

## CL10C751JB8NNNC
designator C?  Capacitance: 750pF  (hidden comment: *)
Capacitor, Ceramic (MLCC), 750pF, ±5%, 50V, C0G, ±5%, SMD 0603; Manufacturer: Samsung Electro-Mechanics; Manufacturer Part Number: CL10C751JB8NNNC
footprint CAP-0603 (0603 (1608M) Capacitor)
pins: 1, 2

## CL10C820JB8NNNC
designator C?  Capacitance: 82pF  (hidden comment: *)
Capacitor, Ceramic (MLCC), 82pF, ±5%, 50V, C0G, ±5%, SMD 0603; Manufacturer: Samsung Electro-Mechanics; Manufacturer Part Number: CL10C820JB8NNNC
footprint CAP-0603 (0603 (1608M) Capacitor)
pins: 1, 2

## CL10C820JB81PNC
designator C?  Capacitance: 82pF  (hidden comment: *)
Capacitor, Ceramic (MLCC), 82pF, ±5%, 50V, C0G, ±5%, SMD 0603; Manufacturer: Samsung Electro-Mechanics; Manufacturer Part Number: CL10C820JB81PNC
footprint CAP-0603 (0603 (1608M) Capacitor)
pins: 1, 2

## CL10C821JB8NNNC
designator C?  Capacitance: 820pF  (hidden comment: *)
Capacitor, Ceramic (MLCC), 820pF, ±5%, 50V, C0G, ±5%, SMD 0603; Manufacturer: Samsung Electro-Mechanics; Manufacturer Part Number: CL10C821JB8NNNC
footprint CAP-0603 (0603 (1608M) Capacitor)
pins: 1, 2

## CL10CR68BB8NNNC
designator C?  Capacitance: 0.68pF  (hidden comment: *)
Capacitor, Ceramic (MLCC), 0.68pF, ±0.1pF, 50V, C0G, ±0.1pF, SMD 0603; Manufacturer: Samsung Electro-Mechanics; Manufacturer Part Number: CL10CR68BB8NNNC
footprint CAP-0603 (0603 (1608M) Capacitor)
pins: 1, 2

## CL10CR75BB8NNNC
designator C?  Capacitance: 0.75pF  (hidden comment: *)
Capacitor, Ceramic (MLCC), 0.75pF, ±0.1pF, 50V, C0G, ±0.1pF, SMD 0603; Manufacturer: Samsung Electro-Mechanics; Manufacturer Part Number: CL10CR75BB8NNNC
footprint CAP-0603 (0603 (1608M) Capacitor)
pins: 1, 2

## CL10CR75CB8NNNC
designator C?  Capacitance: 0.75pF  (hidden comment: *)
Capacitor, Ceramic (MLCC), 0.75pF, ±0.25pF, 50V, C0G, ±0.25pF, SMD 0603; Manufacturer: Samsung Electro-Mechanics; Manufacturer Part Number: CL10CR75CB8NNNC
footprint CAP-0603 (0603 (1608M) Capacitor)
pins: 1, 2

## CL10F104ZA8NNNC
designator C?  Capacitance: 100nF  (hidden comment: *)
Capacitor, Ceramic (MLCC), 100nF, 25V, Y5V, SMD 0603; Manufacturer: Samsung Electro-Mechanics; Manufacturer Part Number: CL10F104ZA8NNNC; Temperature Rating: -20%~+80%
footprint CAP-0603 (0603 (1608M) Capacitor)
pins: 1, 2

## CL10F224ZA8NNNC
designator C?  Capacitance: 220nF  (hidden comment: *)
Capacitor, Ceramic (MLCC), 220nF, 25V, Y5V, SMD 0603; Manufacturer: Samsung Electro-Mechanics; Manufacturer Part Number: CL10F224ZA8NNNC; Temperature Rating: -20%~+80%
footprint CAP-0603 (0603 (1608M) Capacitor)
pins: 1, 2

## CL10F224ZO8NNNC
designator C?  Capacitance: 220nF  (hidden comment: *)
Capacitor, Ceramic (MLCC), 220nF, 16V, Y5V, SMD 0603; Manufacturer: Samsung Electro-Mechanics; Manufacturer Part Number: CL10F224ZO8NNNC; Temperature Rating: -20%~+80%
footprint CAP-0603 (0603 (1608M) Capacitor)
pins: 1, 2

## CL10F333ZB8NNNC
designator C?  Capacitance: 33nF  (hidden comment: *)
Capacitor, Ceramic (MLCC), 33nF, 50V, Y5V, SMD 0603; Manufacturer: Samsung Electro-Mechanics; Manufacturer Part Number: CL10F333ZB8NNNC; Temperature Rating: -20%~+80%
footprint CAP-0603 (0603 (1608M) Capacitor)
pins: 1, 2

## CL10F473ZB8NNNC
designator C?  Capacitance: 47nF  (hidden comment: *)
Capacitor, Ceramic (MLCC), 47nF, 50V, Y5V, SMD 0603; Manufacturer: Samsung Electro-Mechanics; Manufacturer Part Number: CL10F473ZB8NNNC; Temperature Rating: -20%~+80%
footprint CAP-0603 (0603 (1608M) Capacitor)
pins: 1, 2

## CL10F474ZA8NNNC
designator C?  Capacitance: 470nF  (hidden comment: *)
Capacitor, Ceramic (MLCC), 470nF, 25V, Y5V, SMD 0603; Manufacturer: Samsung Electro-Mechanics; Manufacturer Part Number: CL10F474ZA8NNNC; Temperature Rating: -20%~+80%
footprint CAP-0603 (0603 (1608M) Capacitor)
pins: 1, 2

## CL10F474ZB8NNNC
designator C?  Capacitance: 470nF  (hidden comment: *)
Capacitor, Ceramic (MLCC), 470nF, 50V, Y5V, SMD 0603; Manufacturer: Samsung Electro-Mechanics; Manufacturer Part Number: CL10F474ZB8NNNC; Temperature Rating: -20%~+80%
footprint CAP-0603 (0603 (1608M) Capacitor)
pins: 1, 2

## CL10F474ZO8NNNC
designator C?  Capacitance: 470nF  (hidden comment: *)
Capacitor, Ceramic (MLCC), 470nF, 16V, Y5V, SMD 0603; Manufacturer: Samsung Electro-Mechanics; Manufacturer Part Number: CL10F474ZO8NNNC; Temperature Rating: -20%~+80%
footprint CAP-0603 (0603 (1608M) Capacitor)
pins: 1, 2

## CL10X105KO8NNPC
designator C?  Capacitance: 1uF  (hidden comment: *)
Capacitor, Ceramic (MLCC), 1uF, ±10%, 16V, X6S, ±10%, SMD 0603; Manufacturer: Samsung Electro-Mechanics; Manufacturer Part Number: CL10X105KO8NNPC
footprint CAP-0603 (0603 (1608M) Capacitor)
pins: 1, 2

## CL10X106MP8NRNC
designator C?  Capacitance: 10uF  (hidden comment: *)
Capacitor, Ceramic (MLCC), 10uF, ±20%, 10V, X6S, ±20%, SMD 0603; Manufacturer: Samsung Electro-Mechanics; Manufacturer Part Number: CL10X106MP8NRNC
footprint CAP-0603 (0603 (1608M) Capacitor)
pins: 1, 2

## CL10X106MQ8NNNC
designator C?  Capacitance: 10uF  (hidden comment: *)
Capacitor, Ceramic (MLCC), 10uF, ±20%, 6.3V, X6S, ±20%, SMD 0603; Manufacturer: Samsung Electro-Mechanics; Manufacturer Part Number: CL10X106MQ8NNNC
footprint CAP-0603 (0603 (1608M) Capacitor)
pins: 1, 2

## CL10X106MQ8NQPC
designator C?  Capacitance: 10uF  (hidden comment: *)
Capacitor, Ceramic (MLCC), 10uF, ±20%, 6.3V, X6S, ±20%, SMD 0603; Manufacturer: Samsung Electro-Mechanics; Manufacturer Part Number: CL10X106MQ8NQPC
footprint CAP-0603 (0603 (1608M) Capacitor)
pins: 1, 2

## CL10X106MR8NNNC
designator C?  Capacitance: 10uF  (hidden comment: *)
Capacitor, Ceramic (MLCC), 10uF, ±20%, 4V, X6S, ±20%, SMD 0603; Manufacturer: Samsung Electro-Mechanics; Manufacturer Part Number: CL10X106MR8NNNC
footprint CAP-0603 (0603 (1608M) Capacitor)
pins: 1, 2

## CL10X475KQ8NNNC
designator C?  Capacitance: 4.7uF  (hidden comment: *)
Capacitor, Ceramic (MLCC), 4.7uF, ±10%, 6.3V, X6S, ±10%, SMD 0603; Manufacturer: Samsung Electro-Mechanics; Manufacturer Part Number: CL10X475KQ8NNNC
footprint CAP-0603 (0603 (1608M) Capacitor)
pins: 1, 2

## CL10Y225KP84PNC
designator C?  Capacitance: 2.2uF  (hidden comment: *)
Capacitor, Ceramic (MLCC), 2.2uF, ±10%, 10V, X7S, ±10%, SMD 0603; Manufacturer: Samsung Electro-Mechanics; Manufacturer Part Number: CL10Y225KP84PNC
footprint CAP-0603 (0603 (1608M) Capacitor)
pins: 1, 2

## CS0603KRX7R9BB103
designator C?  Capacitance: 10nF  (hidden comment: *)
Capacitor, Ceramic (MLCC), 10nF, ±10%, 50V, X7R, ±10%, SMD 0603; Manufacturer: YAGEO; Manufacturer Part Number: CS0603KRX7R9BB103
footprint CAP-0603 (0603 (1608M) Capacitor)
pins: 1, 2

## CS0603KRX7R9BB222
designator C?  Capacitance: 2.2nF  (hidden comment: *)
Capacitor, Ceramic (MLCC), 2.2nF, ±10%, 50V, X7R, ±10%, SMD 0603; Manufacturer: YAGEO; Manufacturer Part Number: CS0603KRX7R9BB222
footprint CAP-0603 (0603 (1608M) Capacitor)
pins: 1, 2

## CS0603KRX7R9BB332
designator C?  Capacitance: 3.3nF  (hidden comment: *)
Capacitor, Ceramic (MLCC), 3.3nF, ±10%, 50V, X7R, ±10%, SMD 0603; Manufacturer: YAGEO; Manufacturer Part Number: CS0603KRX7R9BB332
footprint CAP-0603 (0603 (1608M) Capacitor)
pins: 1, 2

## CS1608X5R105K250NRB
designator C?  Capacitance: 1uF  (hidden comment: *)
Capacitor, Ceramic (MLCC), 1uF, ±10%, 25V, X5R, ±10%, SMD 0603; Manufacturer: Samwha Capacitor; Manufacturer Part Number: CS1608X5R105K250NRB
footprint CAP-0603 (0603 (1608M) Capacitor)
pins: 1, 2

## CS1608X5R106M160NRB
designator C?  Capacitance: 10uF  (hidden comment: *)
Capacitor, Ceramic (MLCC), 10uF, ±20%, 16V, X5R, ±20%, SMD 0603; Manufacturer: Samwha Capacitor; Manufacturer Part Number: CS1608X5R106M160NRB
footprint CAP-0603 (0603 (1608M) Capacitor)
pins: 1, 2

## CS1608X7R105K250NRB
designator C?  Capacitance: 1uF  (hidden comment: *)
Capacitor, Ceramic (MLCC), 1uF, ±10%, 25V, X7R, ±10%, SMD 0603; Manufacturer: Samwha Capacitor; Manufacturer Part Number: CS1608X7R105K250NRB
footprint CAP-0603 (0603 (1608M) Capacitor)
pins: 1, 2

## CS1608X7R225K100NRB
designator C?  Capacitance: 2.2uF  (hidden comment: *)
Capacitor, Ceramic (MLCC), 2.2uF, ±10%, 10V, X7R, ±10%, SMD 0603; Manufacturer: Samwha Capacitor; Manufacturer Part Number: CS1608X7R225K100NRB
footprint CAP-0603 (0603 (1608M) Capacitor)
pins: 1, 2

## CS1608X7R225M100NRB
designator C?  Capacitance: 2.2uF  (hidden comment: *)
Capacitor, Ceramic (MLCC), 2.2uF, ±20%, 10V, X7R, ±20%, SMD 0603; Manufacturer: Samwha Capacitor; Manufacturer Part Number: CS1608X7R225M100NRB
footprint CAP-0603 (0603 (1608M) Capacitor)
pins: 1, 2

## CS1608X7R334K250NRB
designator C?  Capacitance: 330nF  (hidden comment: *)
Capacitor, Ceramic (MLCC), 330nF, ±10%, 25V, X7R, ±10%, SMD 0603; Manufacturer: Samwha Capacitor; Manufacturer Part Number: CS1608X7R334K250NRB
footprint CAP-0603 (0603 (1608M) Capacitor)
pins: 1, 2

## EMK107ABJ225KAHT
designator C?  Capacitance: 2.2uF  (hidden comment: *)
Capacitor, Ceramic (MLCC), 2.2uF, ±10%, 16V, X5R, ±10%, SMD 0603; Manufacturer: Taiyo Yuden; Manufacturer Part Number: EMK107ABJ225KAHT
footprint CAP-0603 (0603 (1608M) Capacitor)
pins: 1, 2

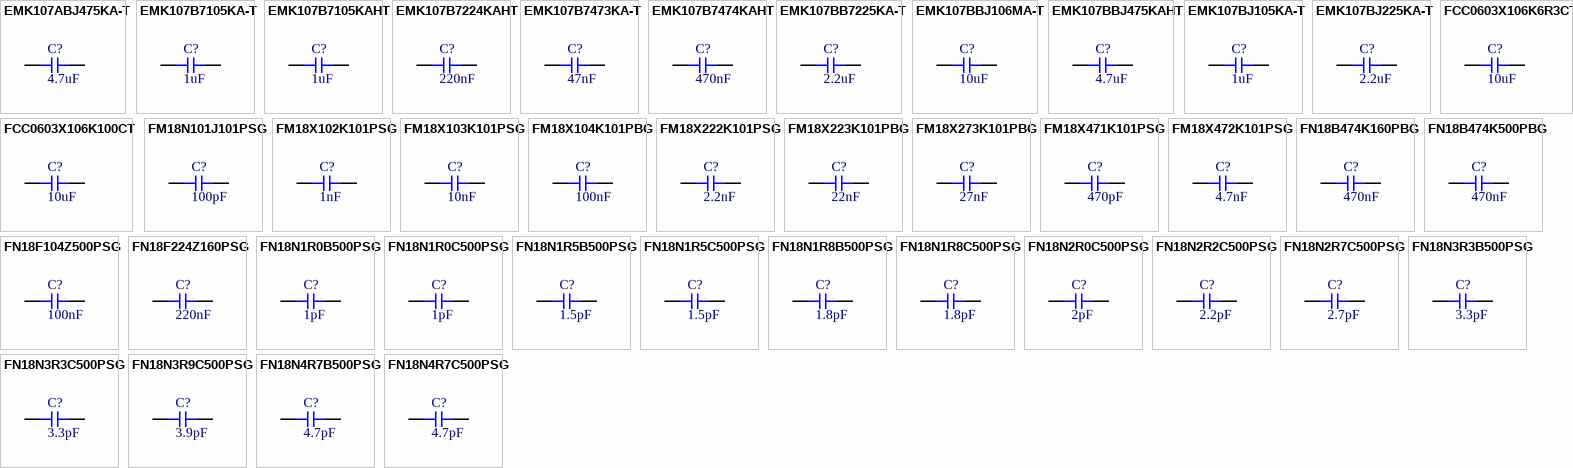
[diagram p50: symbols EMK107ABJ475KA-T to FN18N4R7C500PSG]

## EMK107ABJ475KA-T
designator C?  Capacitance: 4.7uF  (hidden comment: *)
Capacitor, Ceramic (MLCC), 4.7uF, ±10%, 16V, X5R, ±10%, SMD 0603; Manufacturer: Taiyo Yuden; Manufacturer Part Number: EMK107ABJ475KA-T
footprint CAP-0603 (0603 (1608M) Capacitor)
pins: 1, 2

## EMK107B7105KA-T
designator C?  Capacitance: 1uF  (hidden comment: *)
Capacitor, Ceramic (MLCC), 1uF, ±10%, 16V, X7R, ±10%, SMD 0603; Manufacturer: Taiyo Yuden; Manufacturer Part Number: EMK107B7105KA-T
footprint CAP-0603 (0603 (1608M) Capacitor)
pins: 1, 2

## EMK107B7105KAHT
designator C?  Capacitance: 1uF  (hidden comment: *)
Capacitor, Ceramic (MLCC), 1uF, ±10%, 16V, X7R, ±10%, SMD 0603; Manufacturer: Taiyo Yuden; Manufacturer Part Number: EMK107B7105KAHT
footprint CAP-0603 (0603 (1608M) Capacitor)
pins: 1, 2

## EMK107B7224KAHT
designator C?  Capacitance: 220nF  (hidden comment: *)
Capacitor, Ceramic (MLCC), 220nF, ±10%, 16V, X7R, ±10%, SMD 0603; Manufacturer: Taiyo Yuden; Manufacturer Part Number: EMK107B7224KAHT
footprint CAP-0603 (0603 (1608M) Capacitor)
pins: 1, 2

## EMK107B7473KA-T
designator C?  Capacitance: 47nF  (hidden comment: *)
Capacitor, Ceramic (MLCC), 47nF, ±10%, 16V, X7R, ±10%, SMD 0603; Manufacturer: Taiyo Yuden; Manufacturer Part Number: EMK107B7473KA-T
footprint CAP-0603 (0603 (1608M) Capacitor)
pins: 1, 2

## EMK107B7474KAHT
designator C?  Capacitance: 470nF  (hidden comment: *)
Capacitor, Ceramic (MLCC), 470nF, ±10%, 16V, X7R, ±10%, SMD 0603; Manufacturer: Taiyo Yuden; Manufacturer Part Number: EMK107B7474KAHT
footprint CAP-0603 (0603 (1608M) Capacitor)
pins: 1, 2

## EMK107BB7225KA-T
designator C?  Capacitance: 2.2uF  (hidden comment: *)
Capacitor, Ceramic (MLCC), 2.2uF, ±10%, 16V, X7R, ±10%, SMD 0603; Manufacturer: Taiyo Yuden; Manufacturer Part Number: EMK107BB7225KA-T
footprint CAP-0603 (0603 (1608M) Capacitor)
pins: 1, 2

## EMK107BBJ106MA-T
designator C?  Capacitance: 10uF  (hidden comment: *)
Capacitor, Ceramic (MLCC), 10uF, ±20%, 16V, X5R, ±20%, SMD 0603; Manufacturer: Taiyo Yuden; Manufacturer Part Number: EMK107BBJ106MA-T
footprint CAP-0603 (0603 (1608M) Capacitor)
pins: 1, 2

## EMK107BBJ475KAHT
designator C?  Capacitance: 4.7uF  (hidden comment: *)
Capacitor, Ceramic (MLCC), 4.7uF, ±10%, 16V, X5R, ±10%, SMD 0603; Manufacturer: Taiyo Yuden; Manufacturer Part Number: EMK107BBJ475KAHT
footprint CAP-0603 (0603 (1608M) Capacitor)
pins: 1, 2

## EMK107BJ105KA-T
designator C?  Capacitance: 1uF  (hidden comment: *)
Capacitor, Ceramic (MLCC), 1uF, ±10%, 16V, X5R, ±10%, SMD 0603; Manufacturer: Taiyo Yuden; Manufacturer Part Number: EMK107BJ105KA-T
footprint CAP-0603 (0603 (1608M) Capacitor)
pins: 1, 2

## EMK107BJ225KA-T
designator C?  Capacitance: 2.2uF  (hidden comment: *)
Capacitor, Ceramic (MLCC), 2.2uF, ±10%, 16V, X5R, ±10%, SMD 0603; Manufacturer: Taiyo Yuden; Manufacturer Part Number: EMK107BJ225KA-T
footprint CAP-0603 (0603 (1608M) Capacitor)
pins: 1, 2

## FCC0603X106K6R3CT
designator C?  Capacitance: 10uF  (hidden comment: *)
Capacitor, Ceramic (MLCC), 10uF, ±10%, 6.3V, X5R, ±10%, SMD 0603; Manufacturer: FOJAN; Manufacturer Part Number: FCC0603X106K6R3CT
footprint CAP-0603 (0603 (1608M) Capacitor)
pins: 1, 2

## FCC0603X106K100CT
designator C?  Capacitance: 10uF  (hidden comment: *)
Capacitor, Ceramic (MLCC), 10uF, ±10%, 10V, X5R, ±10%, SMD 0603; Manufacturer: FOJAN; Manufacturer Part Number: FCC0603X106K100CT
footprint CAP-0603 (0603 (1608M) Capacitor)
pins: 1, 2

## FM18N101J101PSG
designator C?  Capacitance: 100pF  (hidden comment: *)
Capacitor, Ceramic (MLCC), 100pF, ±5%, 100V, C0G, ±5%, SMD 0603; Manufacturer: PSA(Prosperity Dielectrics); Manufacturer Part Number: FM18N101J101PSG
footprint CAP-0603 (0603 (1608M) Capacitor)
pins: 1, 2

## FM18X102K101PSG
designator C?  Capacitance: 1nF  (hidden comment: *)
Capacitor, Ceramic (MLCC), 1nF, ±10%, 100V, X7R, ±10%, SMD 0603; Manufacturer: PSA(Prosperity Dielectrics); Manufacturer Part Number: FM18X102K101PSG
footprint CAP-0603 (0603 (1608M) Capacitor)
pins: 1, 2

## FM18X103K101PSG
designator C?  Capacitance: 10nF  (hidden comment: *)
Capacitor, Ceramic (MLCC), 10nF, ±10%, 100V, X7R, ±10%, SMD 0603; Manufacturer: PSA(Prosperity Dielectrics); Manufacturer Part Number: FM18X103K101PSG
footprint CAP-0603 (0603 (1608M) Capacitor)
pins: 1, 2

## FM18X104K101PBG
designator C?  Capacitance: 100nF  (hidden comment: *)
Capacitor, Ceramic (MLCC), 100nF, ±10%, 100V, X7R, ±10%, SMD 0603; Manufacturer: PSA(Prosperity Dielectrics); Manufacturer Part Number: FM18X104K101PBG
footprint CAP-0603 (0603 (1608M) Capacitor)
pins: 1, 2

## FM18X222K101PSG
designator C?  Capacitance: 2.2nF  (hidden comment: *)
Capacitor, Ceramic (MLCC), 2.2nF, ±10%, 100V, X7R, ±10%, SMD 0603; Manufacturer: PSA(Prosperity Dielectrics); Manufacturer Part Number: FM18X222K101PSG
footprint CAP-0603 (0603 (1608M) Capacitor)
pins: 1, 2

## FM18X223K101PBG
designator C?  Capacitance: 22nF  (hidden comment: *)
Capacitor, Ceramic (MLCC), 22nF, ±10%, 100V, X7R, ±10%, SMD 0603; Manufacturer: PSA(Prosperity Dielectrics); Manufacturer Part Number: FM18X223K101PBG
footprint CAP-0603 (0603 (1608M) Capacitor)
pins: 1, 2

## FM18X273K101PBG
designator C?  Capacitance: 27nF  (hidden comment: *)
Capacitor, Ceramic (MLCC), 27nF, ±10%, 100V, X7R, ±10%, SMD 0603; Manufacturer: PSA(Prosperity Dielectrics); Manufacturer Part Number: FM18X273K101PBG
footprint CAP-0603 (0603 (1608M) Capacitor)
pins: 1, 2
